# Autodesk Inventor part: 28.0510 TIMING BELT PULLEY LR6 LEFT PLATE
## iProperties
Created: 2007-06
Part Number: 28.0510 TIMING BELT PULLEY LR6 LEFT PLATE
Document SubType Name: Modeling
Designer: Andy Moles
Material: Aluminum-6061
Mass: 286.546 g
Surface Area: 352.02 cm^2
Volume: 105.736 cm^3
Density: 2.71 g/cm^3
Author: Andy Moles
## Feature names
1. Extrusion1
2. Hole1
3. Hole2
4. Extrusion2
5. Extrusion3
6. Extrusion4
7. Extrusion5
8. Extrusion6
9. Fillet1
10. Extrusion7
11. Extrusion8
12. Extrusion9
13. Extrusion10
14. Hole3
15. Extrusion11
16. Extrusion12
17. Extrusion13
18. Hole4
19. Extrusion14
20. Extrusion15
21. Extrusion16
